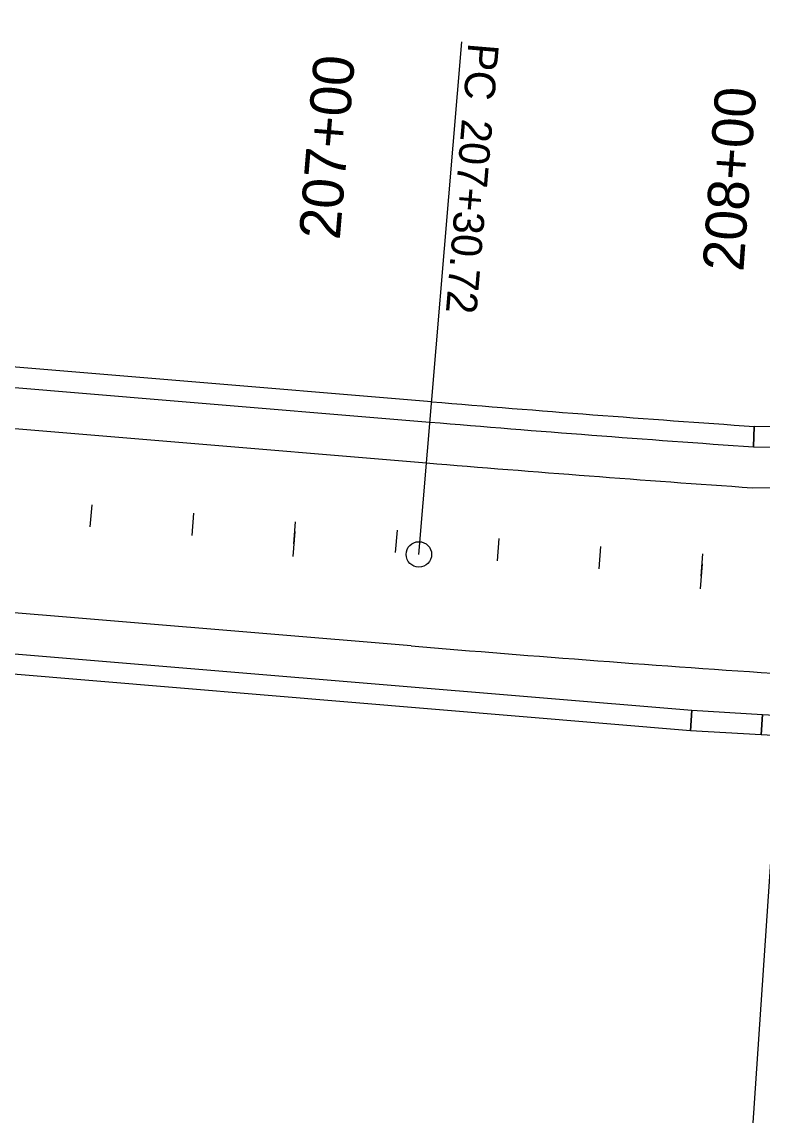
# Model space of a CAD drawing. Extents: x 20499216 to 20505321, y 7953487 to 7960535.
# Drawn here: x 20504332.5 to 20504513.8, y 7953528.2 to 7953797.8 of the extents above; entities that cross this region are included whole.
import ezdxf

# ---------------------------------------------------------------- set-up
doc = ezdxf.new("R2010")
doc.units = 0
for name, color, linetype in [('Drainage', 7, 'Continuous'), ('EXT_CU', 7, 'Continuous'), ('EXT_RR', 7, 'Continuous'), ('NamedBoundary', 7, 'Continuous'), ('Natural', 7, 'Continuous'), ('Safety', 7, 'Continuous')]:
    doc.layers.add(name, color=color, linetype=linetype)

msp = doc.modelspace()

# ---------------------------------------------------------------- linework, layer by layer
at = {"layer": 'Drainage'}
msp.add_lwpolyline([(20504513.39, 7953623.25), (20504513.68, 7953628.24), (20504528.65, 7953627.38), (20504528.36, 7953622.39)], close=True, dxfattribs=at)
at = {"layer": 'EXT_CU'}
msp.add_line((20504511.5, 7953693.76), (20504511.66, 7953698.76), dxfattribs=at)
for points in [[(20504432.72, 7953704.8), (20504368.14, 7953710.18), (20504368.14, 7953710.18), (20504272.08, 7953718.2), (20504272.15, 7953713.17), (20504367.73, 7953705.2), (20504367.73, 7953705.2), (20504432.3, 7953699.81)], [(20504538.83, 7953698.3), (20504511.66, 7953698.76), (20504511.5, 7953693.76), (20504535.8, 7953693.34)]]:
    msp.add_lwpolyline(points, dxfattribs=at)
for points in [[(20504266.74, 7953648.4), (20504496.4, 7953629.24), (20504496.05, 7953624.25), (20504265.83, 7953643.46)], [(20504496.05, 7953624.25), (20504496.4, 7953629.24), (20504513.68, 7953628.24), (20504513.39, 7953623.25)]]:
    msp.add_lwpolyline(points, close=True, dxfattribs=at)
for radius, end in [(5692.5, 266.02776), (5697.5, 266.02959)]:
    msp.add_arc((20504906, 7959377.59), radius, 265.23083, end, dxfattribs=at)
at = {"layer": 'EXT_RR'}
for p, q in [((20504349.16, 7953674.14), (20504349.62, 7953679.58)), ((20504374.08, 7953672.06), (20504374.53, 7953677.5)), ((20504399.24, 7953673.03), (20504398.73, 7953666.93)), ((20504423.9, 7953667.9), (20504424.36, 7953673.34)), ((20504448.82, 7953665.85), (20504449.25, 7953671.3)), ((20504473.74, 7953663.91), (20504474.15, 7953669.36)), ((20504498.89, 7953665.13), (20504498.46, 7953659.03))]:
    msp.add_line(p, q, dxfattribs=at)
at = {"layer": 'NamedBoundary'}
for points in [[(20503281.84, 7953797.82), (20503630.7, 7953768.71), (20503809.08, 7953741.78), (20504366.9, 7953695.23), (20504431.47, 7953689.85)], [(20504427.73, 7953645), (20504246.09, 7953660.16), (20503289.01, 7953740.03), (20503289.01, 7953740.03)], [(20504511.17, 7953683.76), (20504707.3, 7953684.41), (20504705.81, 7953658.14), (20504696.22, 7953658.54), (20504695.12, 7953642.6), (20504704.87, 7953641.64), (20504703.39, 7953615.5), (20504596.48, 7953633.27)]]:
    msp.add_lwpolyline(points, dxfattribs=at)
for centre, radius, start, end in [((20504905.79, 7959374.87), 5704.78, 265.23064, 266.03342), ((20504900.74, 7959314.54), 5689.23, 265.23083, 266.15356)]:
    msp.add_arc(centre, radius, start, end, dxfattribs=at)
at = {"layer": 'Natural'}
for p, q in [((20504429.6, 7953667.42), (20504440.08, 7953792.99)), ((20504440.08, 7953792.99), (20504440.08, 7953792.99)), ((20504520.19, 7953659.87), (20504511.3, 7953528.17)), ((20504511.3, 7953528.17), (20504511.3, 7953528.17))]:
    msp.add_line(p, q, dxfattribs=at)
msp.add_circle((20504429.6, 7953667.42), 3.12, dxfattribs=at)
at = {"layer": 'Safety'}
for p, q in [((20504398.99, 7953669.98), (20504399.44, 7953675.42)), ((20504498.68, 7953662.08), (20504499.06, 7953667.53))]:
    msp.add_line(p, q, dxfattribs=at)

# ---------------------------------------------------------------- texts
at = {"layer": 'EXT_RR'}
for s, rotation, p in [('207+00', 85.2308, (20504410.22, 7953744.3)), ('208+00', 85.9236, (20504509, 7953736.54))]:
    msp.add_text(s, height=10.02, rotation=rotation, dxfattribs=at).set_placement(p)
at = {"layer": 'Natural'}
for s, p in [('PC', (20504441.72, 7953792.85)), ('207+30.72', (20504440.16, 7953774.24))]:
    msp.add_text(s, height=7.5, rotation=265.2308, dxfattribs=at).set_placement(p)

doc.saveas('drawing.dxf')
